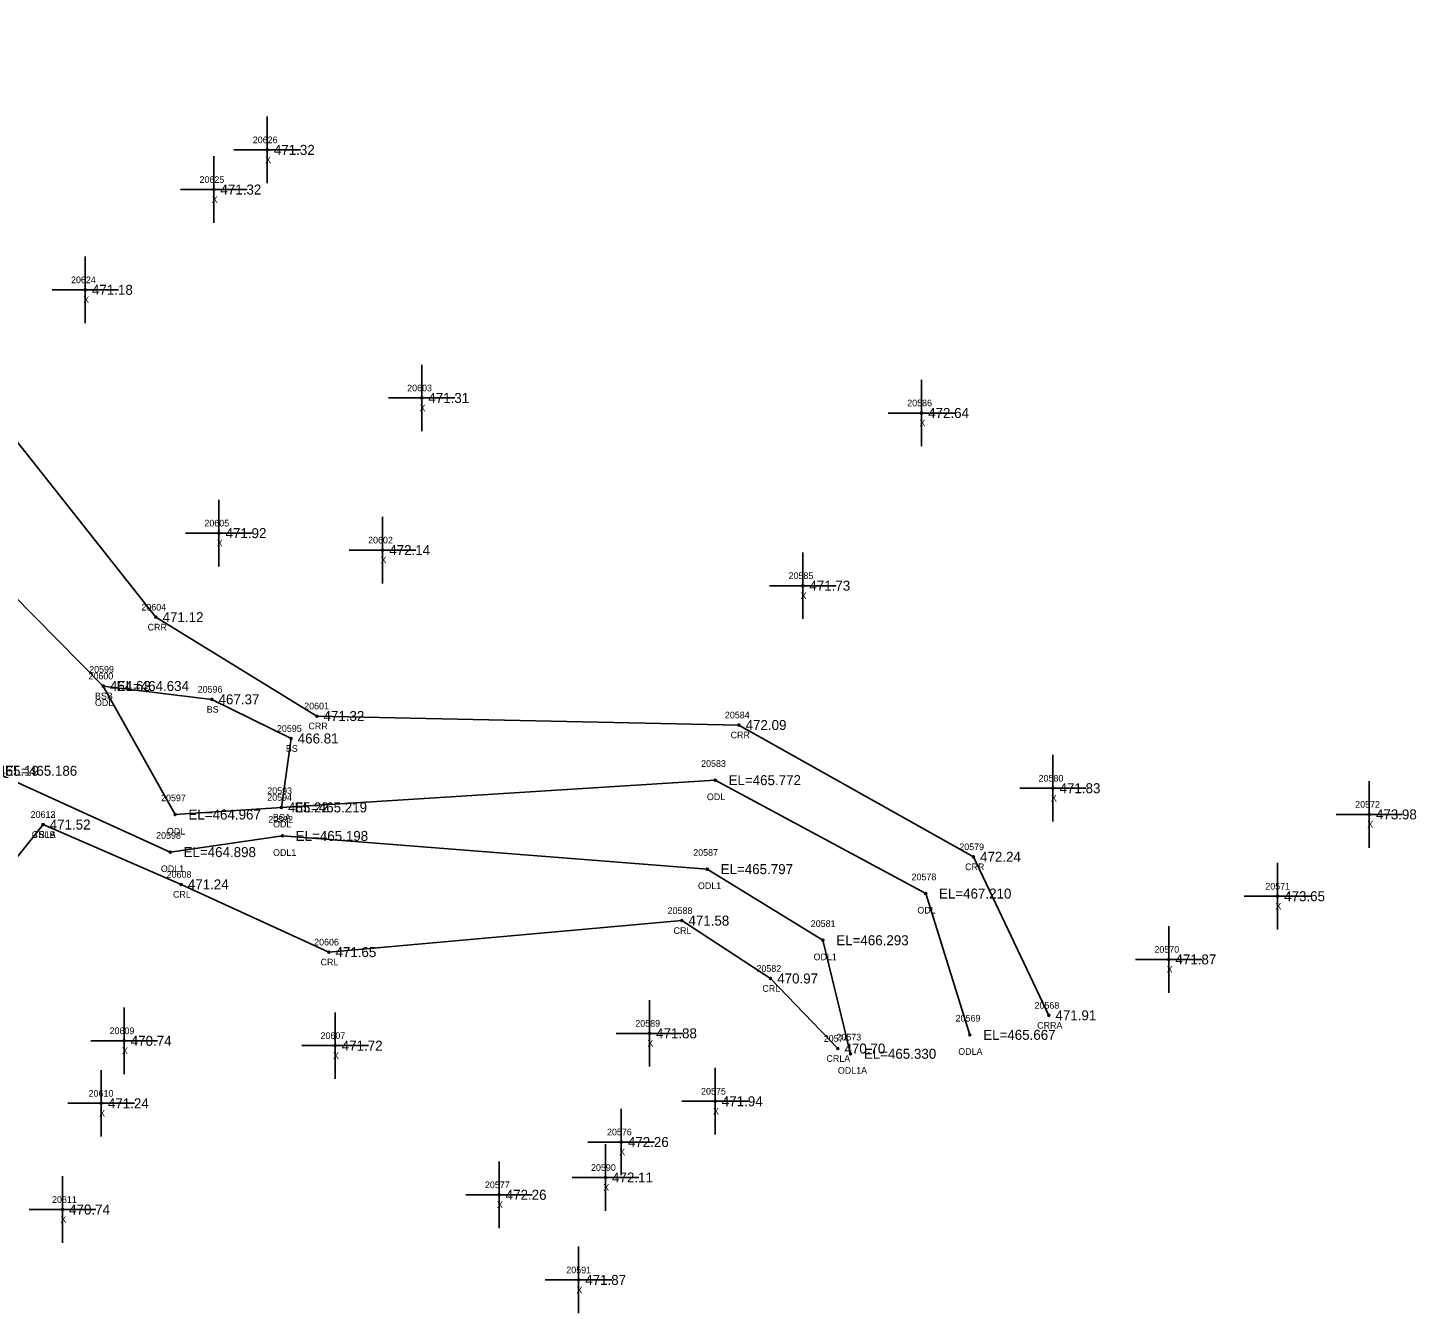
# Model space of a CAD drawing. Extents: x 1741010 to 1742139, y 749382 to 750625.
# Drawn here: x 1741856.4 to 1742064.9, y 749655.2 to 749848.2 of the extents above; entities that cross this region are included whole.
import ezdxf

# ---------------------------------------------------------------- set-up
doc = ezdxf.new("R2010")
doc.units = 0
for name, color, linetype in [('RD_DTM_BkLn2', 7, 'Continuous'), ('RD_DTM_BkLn_txCode', 7, 'Continuous'), ('RD_EX_H2O', 7, 'Continuous'), ('RD_EX_H2O_txCode', 7, 'Continuous'), ('RD_EX_Misc', 7, 'Continuous'), ('RD_EX_Misc_txCode', 7, 'Continuous'), ('RD_EX_TX_H2O_ELEV', 7, 'Continuous'), ('RD_EX_TX_Misc_ELEV', 7, 'Continuous'), ('RD_SMD_Locator', 7, 'Continuous')]:
    doc.layers.add(name, color=color, linetype=linetype)

msp = doc.modelspace()

# ---------------------------------------------------------------- linework, layer by layer
at = {"layer": 'RD_DTM_BkLn2'}
for points in [[(1741894.45, 749731.15), (1741895.91, 749741.5), (1741884.02, 749747.38), (1741867.7, 749749.38)], [(1741858.65, 749728.58), (1741847.81, 749715.02), (1741837.58, 749703.8), (1741833.3, 749723.2), (1741846.63, 749736.99)]]:
    msp.add_lwpolyline(points, dxfattribs=at)
at = {"layer": 'RD_EX_H2O'}
for points in [[(1742009.73, 749699.92), (1741998.41, 749723.73), (1741963.19, 749743.52), (1741899.78, 749744.87), (1741875.61, 749759.72), (1741846.8, 749796.06), (1741820.86, 749838.72), (1741812.23, 749854.24), (1741798.02, 749868.34), (1741757.86, 749894.19), (1741733.12, 749942.57), (1741724.29, 749959.1), (1741692.79, 749978.15), (1741670.02, 749986.94), (1741660.12, 749986.72), (1741653.47, 749993.98), (1741643.26, 750008.63), (1741623.07, 750045.53)], [(1741979.95, 749694.15), (1741975.81, 749711.2), (1741958.44, 749721.88), (1741894.61, 749726.87), (1741877.76, 749724.44), (1741850.91, 749736.65), (1741828.26, 749780.7), (1741797.14, 749817.35), (1741808.22, 749831.81), (1741810.09, 749840.16), (1741785.92, 749848.46), (1741738.7, 749880.42), (1741729.53, 749896.38), (1741713.46, 749926.44), (1741709.24, 749941.41), (1741681.29, 749963.78), (1741670.93, 749974.67), (1741649.76, 749966.83), (1741639.61, 749974.72), (1741630.05, 749994.96), (1741605.22, 750035.39), (1741604.28, 750042.48)], [(1741997.88, 749696.99), (1741991.24, 749718.21), (1741959.63, 749735.24), (1741894.45, 749731.15), (1741878.5, 749730.08), (1741867.7, 749749.38), (1741830.02, 749787.48), (1741810.47, 749825.74), (1741816.53, 749831.94), (1741813.36, 749842.06), (1741786.5, 749855.75), (1741743.5, 749885.54), (1741743.36, 749896.22), (1741733.61, 749897.85), (1741720.42, 749929.78), (1741722.99, 749946.15), (1741719.27, 749955.78), (1741689.88, 749975.02), (1741668.65, 749983.88), (1741656.91, 749978.01), (1741649.96, 749989.33), (1741640.41, 750007.7), (1741621.8, 750037.62), (1741614.56, 750040.31)], [(1741978.04, 749694.94), (1741967.94, 749705.46), (1741954.6, 749714.15), (1741901.58, 749709.42), (1741879.4, 749719.59), (1741858.65, 749728.58)]]:
    msp.add_lwpolyline(points, dxfattribs=at)
at = {"layer": 'RD_EX_Misc'}
for p, q in [((1741892.33, 749824.9), (1741892.33, 749834.9)), ((1741884.3, 749818.94), (1741884.3, 749828.94)), ((1741887.33, 749829.9), (1741897.33, 749829.9)), ((1741879.3, 749823.94), (1741889.3, 749823.94)), ((1741865, 749803.88), (1741865, 749813.88)), ((1741860, 749808.88), (1741870, 749808.88)), ((1741915.53, 749787.64), (1741915.53, 749797.64)), ((1741990.61, 749785.38), (1741990.61, 749795.38)), ((1741910.53, 749792.64), (1741920.53, 749792.64)), ((1741985.61, 749790.38), (1741995.61, 749790.38)), ((1741885.07, 749767.34), (1741885.07, 749777.34)), ((1741909.66, 749764.79), (1741909.66, 749774.79)), ((1741880.07, 749772.34), (1741890.07, 749772.34)), ((1741904.66, 749769.79), (1741914.66, 749769.79)), ((1741972.77, 749759.45), (1741972.77, 749769.45)), ((1741967.77, 749764.45), (1741977.77, 749764.45)), ((1742010.36, 749729.03), (1742010.36, 749739.03)), ((1742057.88, 749725.1), (1742057.88, 749735.1)), ((1742005.36, 749734.03), (1742015.36, 749734.03)), ((1742052.88, 749730.1), (1742062.88, 749730.1)), ((1742044.09, 749712.81), (1742044.09, 749722.81)), ((1742039.09, 749717.81), (1742049.09, 749717.81)), ((1742027.76, 749703.32), (1742027.76, 749713.32)), ((1742022.76, 749708.32), (1742032.76, 749708.32)), ((1741870.83, 749691.1), (1741870.83, 749701.1)), ((1741949.74, 749692.22), (1741949.74, 749702.22)), ((1741902.52, 749690.37), (1741902.52, 749700.37)), ((1741944.74, 749697.22), (1741954.74, 749697.22)), ((1741865.83, 749696.1), (1741875.83, 749696.1)), ((1741897.52, 749695.37), (1741907.52, 749695.37)), ((1741867.4, 749681.71), (1741867.4, 749691.71)), ((1741959.62, 749682.02), (1741959.62, 749692.02)), ((1741862.4, 749686.71), (1741872.4, 749686.71)), ((1741954.62, 749687.02), (1741964.62, 749687.02)), ((1741945.51, 749675.9), (1741945.51, 749685.9)), ((1741940.51, 749680.9), (1741950.51, 749680.9)), ((1741943.13, 749670.57), (1741943.13, 749680.57)), ((1741927.15, 749667.97), (1741927.15, 749677.97)), ((1741861.57, 749665.76), (1741861.57, 749675.76)), ((1741938.13, 749675.57), (1741948.13, 749675.57)), ((1741922.15, 749672.97), (1741932.15, 749672.97)), ((1741856.57, 749670.76), (1741866.57, 749670.76)), ((1741939.1, 749655.19), (1741939.1, 749665.19)), ((1741934.1, 749660.19), (1741944.1, 749660.19))]:
    msp.add_line(p, q, dxfattribs=at)
at = {"layer": 'RD_SMD_Locator'}
for centre in [(1741892.33, 749829.9), (1741884.3, 749823.94), (1741865, 749808.88), (1741915.53, 749792.64), (1741990.61, 749790.38), (1741885.07, 749772.34), (1741909.66, 749769.79), (1741972.77, 749764.45), (1741875.61, 749759.72), (1741867.7, 749749.38), (1741867.7, 749749.38), (1741884.02, 749747.38), (1741899.78, 749744.87), (1741963.19, 749743.52), (1741895.91, 749741.5), (1741959.63, 749735.24), (1742010.36, 749734.03), (1741894.45, 749731.15), (1741894.45, 749731.15), (1741858.65, 749728.58), (1741858.65, 749728.58), (1741878.5, 749730.08), (1742057.88, 749730.1), (1741894.61, 749726.87), (1741877.76, 749724.44), (1741958.44, 749721.88), (1741998.41, 749723.73), (1741879.4, 749719.59), (1741991.24, 749718.21), (1742044.09, 749717.81), (1741954.6, 749714.15), (1741901.58, 749709.42), (1741975.81, 749711.2), (1742027.76, 749708.32), (1741967.94, 749705.46), (1742009.73, 749699.92), (1741949.74, 749697.22), (1741997.88, 749696.99), (1741870.83, 749696.1), (1741902.52, 749695.37), (1741978.04, 749694.94), (1741979.95, 749694.15), (1741867.4, 749686.71), (1741959.62, 749687.02), (1741945.51, 749680.9), (1741943.13, 749675.57), (1741927.15, 749672.97), (1741861.57, 749670.76), (1741939.1, 749660.19)]:
    msp.add_circle(centre, 0.15, dxfattribs=at)

# ---------------------------------------------------------------- texts
at = {"layer": 'RD_DTM_BkLn_txCode'}
for s, p in [('20600', (1741865.48, 749750.38)), ('20596', (1741881.88, 749748.38)), ('BSB', (1741866.45, 749747.38)), ('BS', (1741883.24, 749745.38)), ('20595', (1741893.79, 749742.5)), ('BS', (1741895.13, 749739.5)), ('20594', (1741892.33, 749732.15)), ('20613', (1741856.79, 749729.58)), ('BSA', (1741893.18, 749729.15)), ('TS1A', (1741857.2, 749726.58))]:
    msp.add_text(s, height=1, dxfattribs=at).set_placement(p)
at = {"layer": 'RD_EX_H2O_txCode'}
for s, p in [('20604', (1741873.43, 749760.72)), ('CRR', (1741874.36, 749757.72)), ('20599', (1741865.58, 749751.38)), ('ODL', (1741866.45, 749746.38)), ('20601', (1741897.88, 749745.87)), ('20584', (1741961.08, 749744.52)), ('CRR', (1741898.52, 749742.87)), ('CRR', (1741961.94, 749741.52)), ('20583', (1741957.51, 749737.24)), ('20597', (1741876.38, 749732.08)), ('20593', (1741892.33, 749733.15)), ('ODL', (1741958.38, 749732.24)), ('20612', (1741856.79, 749729.58)), ('20592', (1741892.49, 749728.87)), ('ODL', (1741893.2, 749728.15)), ('CRLB', (1741856.95, 749726.58)), ('20598', (1741875.64, 749726.44)), ('ODL', (1741877.25, 749727.08)), ('ODL1', (1741893.2, 749723.87)), ('20587', (1741956.32, 749723.88)), ('20579', (1741996.29, 749724.73)), ('ODL1', (1741876.35, 749721.44)), ('CRR', (1741997.16, 749721.73)), ('20608', (1741877.22, 749720.59)), ('ODL1', (1741957.03, 749718.88)), ('20578', (1741989.12, 749720.21)), ('CRL', (1741878.17, 749717.59)), ('20588', (1741952.48, 749715.15)), ('ODL', (1741989.99, 749715.21)), ('20581', (1741973.98, 749713.2)), ('CRL', (1741953.37, 749712.15)), ('20606', (1741899.38, 749710.42)), ('CRL', (1741900.35, 749707.42)), ('20582', (1741965.82, 749706.46)), ('ODL1', (1741974.4, 749708.2)), ('CRL', (1741966.71, 749703.46)), ('20568', (1742007.59, 749700.92)), ('20569', (1741995.74, 749698.99)), ('20574', (1741975.93, 749695.94)), ('20573', (1741977.83, 749696.15)), ('CRRA', (1742007.99, 749697.92)), ('ODLA', (1741996.14, 749693.99)), ('CRLA', (1741976.33, 749692.94)), ('ODL1A', (1741978.05, 749691.15))]:
    msp.add_text(s, height=1, dxfattribs=at).set_placement(p)
at = {"layer": 'RD_EX_Misc_txCode'}
for s, p in [('20626', (1741890.16, 749830.9)), ('X', (1741892.01, 749827.9)), ('20625', (1741882.16, 749824.94)), ('X', (1741883.99, 749821.94)), ('20624', (1741862.86, 749809.88)), ('X', (1741864.69, 749806.88)), ('20603', (1741913.35, 749793.64)), ('X', (1741915.21, 749790.64)), ('20586', (1741988.47, 749791.38)), ('X', (1741990.3, 749788.38)), ('20605', (1741882.89, 749773.34)), ('X', (1741884.75, 749770.34)), ('20602', (1741907.48, 749770.79)), ('X', (1741909.34, 749767.79)), ('20585', (1741970.65, 749765.45)), ('X', (1741972.45, 749762.45)), ('20580', (1742008.2, 749735.03)), ('X', (1742010.05, 749732.03)), ('20572', (1742055.76, 749731.1)), ('X', (1742057.57, 749728.1)), ('20571', (1742042.26, 749718.81)), ('X', (1742043.78, 749715.81)), ('20570', (1742025.6, 749709.32)), ('X', (1742027.44, 749706.32)), ('20589', (1741947.62, 749698.22)), ('20609', (1741868.65, 749697.1)), ('20607', (1741900.33, 749696.37)), ('X', (1741870.51, 749694.1)), ('X', (1741949.43, 749695.22)), ('X', (1741902.2, 749693.37)), ('20610', (1741865.5, 749687.71)), ('20575', (1741957.5, 749688.02)), ('X', (1741867.08, 749684.71)), ('X', (1741959.3, 749685.02)), ('20576', (1741943.37, 749681.9)), ('X', (1741945.2, 749678.9)), ('20590', (1741940.97, 749676.57)), ('20577', (1741925.03, 749673.97)), ('X', (1741942.81, 749673.57)), ('20611', (1741860, 749671.76)), ('X', (1741926.84, 749670.97)), ('X', (1741861.26, 749668.76)), ('20591', (1741937.26, 749661.19)), ('X', (1741938.78, 749658.19))]:
    msp.add_text(s, height=1, dxfattribs=at).set_placement(p)
at = {"layer": 'RD_EX_TX_H2O_ELEV'}
for s, p in [('471.12', (1741876.61, 749758.97)), ('EL=464.634', (1741869.7, 749748.63)), ('471.32', (1741900.78, 749744.12)), ('472.09', (1741964.19, 749742.77)), ('EL=465.186', (1741852.91, 749735.9)), ('EL=465.772', (1741961.63, 749734.49)), ('EL=464.967', (1741880.5, 749729.33)), ('EL=465.219', (1741896.45, 749730.4)), ('471.52', (1741859.65, 749727.83)), ('EL=465.198', (1741896.61, 749726.12)), ('EL=464.898', (1741879.76, 749723.69)), ('472.24', (1741999.41, 749722.98)), ('EL=465.797', (1741960.44, 749721.13)), ('471.24', (1741880.4, 749718.84)), ('EL=467.210', (1741993.24, 749717.46)), ('471.58', (1741955.6, 749713.4)), ('EL=466.293', (1741977.81, 749710.45)), ('471.65', (1741902.58, 749708.67)), ('470.97', (1741968.94, 749704.71)), ('471.91', (1742010.73, 749699.17)), ('EL=465.667', (1741999.88, 749696.24)), ('470.70', (1741979.04, 749694.19)), ('EL=465.330', (1741981.95, 749693.4))]:
    msp.add_text(s, height=1.5, dxfattribs=at).set_placement(p)
at = {"layer": 'RD_EX_TX_Misc_ELEV'}
for s, p in [('471.32', (1741893.33, 749829.15)), ('471.32', (1741885.3, 749823.19)), ('471.18', (1741866, 749808.13)), ('471.31', (1741916.53, 749791.89)), ('472.64', (1741991.61, 749789.63)), ('471.92', (1741886.07, 749771.59)), ('472.14', (1741910.66, 749769.04)), ('471.73', (1741973.77, 749763.7)), ('464.63', (1741868.7, 749748.63)), ('467.37', (1741885.02, 749746.63)), ('466.81', (1741896.91, 749740.75)), ('465.19', (1741851.91, 749735.9)), ('471.83', (1742011.36, 749733.28)), ('465.22', (1741895.45, 749730.4)), ('473.98', (1742058.88, 749729.35)), ('471.52', (1741859.65, 749727.83)), ('473.65', (1742045.09, 749717.06)), ('471.87', (1742028.76, 749707.57)), ('471.88', (1741950.74, 749696.47)), ('470.74', (1741871.83, 749695.35)), ('471.72', (1741903.52, 749694.62)), ('471.24', (1741868.4, 749685.96)), ('471.94', (1741960.62, 749686.27)), ('472.26', (1741946.51, 749680.15)), ('472.11', (1741944.13, 749674.82)), ('472.26', (1741928.15, 749672.22)), ('470.74', (1741862.57, 749670.01)), ('471.87', (1741940.1, 749659.44))]:
    msp.add_text(s, height=1.5, dxfattribs=at).set_placement(p)

doc.saveas('drawing.dxf')
